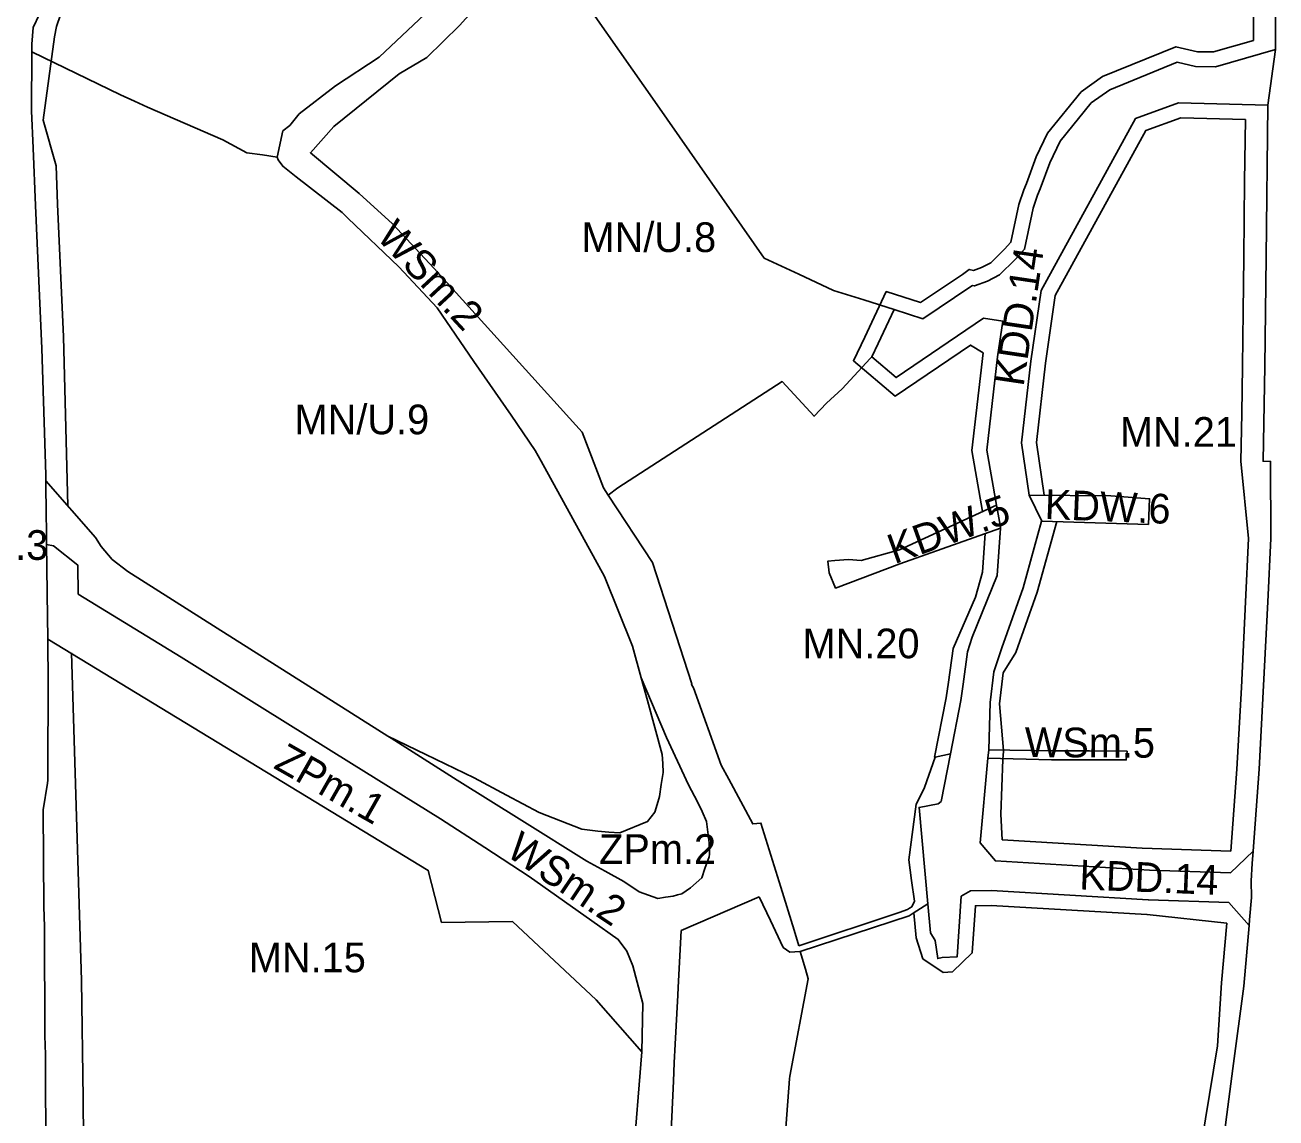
# Model space of a CAD drawing. Extents: x 7431080 to 7433370, y 5546450 to 5548428.
# Drawn here: x 7431653 to 7431989.9, y 5547216.3 to 5547510.7 of the extents above; entities that cross this region are included whole.
import ezdxf

# ---------------------------------------------------------------- set-up
doc = ezdxf.new("R2010")
doc.units = 0
for name, color, linetype in [('Linie Rozgraniczajace', 7, 'Continuous'), ('nieprzekraczalna linia zabudowy', 7, 'Continuous'), ('oznaczenia_przeznaczen', 7, 'Continuous')]:
    doc.layers.add(name, color=color, linetype=linetype)

msp = doc.modelspace()

# ---------------------------------------------------------------- linework, layer by layer
at = {"layer": 'Linie Rozgraniczajace'}
for p, q in [((7431911.15, 5547431.69), (7431916.34, 5547430.94)), ((7431658.88, 5547364.65), (7431658.97, 5547357.52)), ((7431829.74, 5547266.75), (7431850.69, 5547275.88)), ((7431850.69, 5547275.88), (7431853.77, 5547269.44)), ((7431829.74, 5547266.75), (7431828.91, 5547251.44))]:
    msp.add_line(p, q, dxfattribs=at)
for points in [[(7431654.75, 5547487.52), (7431654.85, 5547503.43), (7431654.86, 5547505.49), (7431655.24, 5547510.04), (7431661.99, 5547524.42), (7431663.48, 5547526.4), (7431672.06, 5547534.63), (7431672.08, 5547534.66), (7431672.12, 5547534.69), (7431679.18, 5547541.67), (7431679.27, 5547541.81), (7431679.43, 5547541.93), (7431683.86, 5547546.88), (7431683.88, 5547546.91), (7431684.29, 5547547.41), (7431690.25, 5547555.79), (7431706.15, 5547576.86), (7431734.93, 5547609.85), (7431751.33, 5547628.73)], [(7431989.92, 5547534.61), (7431989.83, 5547504.09), (7431987.71, 5547489.08), (7431987.25, 5547448.13), (7431986.91, 5547418.82), (7431986.45, 5547393.18), (7431988.46, 5547393.1), (7431988.49, 5547372.36), (7431987.7, 5547355.33), (7431985.39, 5547310.25), (7431983.79, 5547288.13), (7431983.55, 5547284.77), (7431983.22, 5547280.11), (7431983.37, 5547275.64), (7431982.82, 5547269.6), (7431982.69, 5547268.13)], [(7431722.46, 5547482.18), (7431724.32, 5547483.59), (7431726.87, 5547486.76), (7431736.59, 5547494.28), (7431748.4, 5547502), (7431779.07, 5547531.01)], [(7431810.1, 5547384.01), (7431808.82, 5547385.97), (7431803.09, 5547401.04), (7431763.17, 5547445.1), (7431751.95, 5547457.15), (7431743.02, 5547465.27), (7431729.86, 5547476.25), (7431736.2, 5547483.32), (7431753.76, 5547497.55), (7431761.26, 5547501.96), (7431770.04, 5547510.52), (7431781.06, 5547522.88), (7431786.34, 5547526.6), (7431796.46, 5547527.5), (7431809.81, 5547528.69)], [(7431852.09, 5547447.88), (7431823.24, 5547489.18), (7431796.46, 5547527.5)], [(7431989.83, 5547504.09), (7431973.64, 5547499.41), (7431968.27, 5547499.5), (7431963.3, 5547500.63), (7431945.13, 5547493.25), (7431940.18, 5547489.7), (7431931.83, 5547479.42), (7431929.03, 5547473.59), (7431926.42, 5547466.52)], [(7431654.85, 5547503.43), (7431678.73, 5547491.84), (7431682.47, 5547490.14), (7431685.99, 5547488.55), (7431696.13, 5547484.12), (7431706.28, 5547479.7), (7431712.79, 5547476.27), (7431716.95, 5547475.66), (7431720.95, 5547475.06)], [(7431657.53, 5547423.57), (7431655.86, 5547462.08), (7431655.17, 5547477.51), (7431654.75, 5547487.52)], [(7431987.71, 5547489.08), (7431963.67, 5547489.69), (7431952.08, 5547485.52), (7431926.64, 5547439.12)], [(7431739.95, 5547458.68), (7431738.42, 5547460.15), (7431726.08, 5547469.74), (7431722.43, 5547472.61), (7431721.17, 5547474.4), (7431720.95, 5547475.06), (7431722.46, 5547482.18)], [(7431926.42, 5547466.52), (7431925.72, 5547464.87), (7431924.54, 5547461.32), (7431922.23, 5547450.26), (7431919.69, 5547447.53), (7431915.47, 5547443.36), (7431912.21, 5547441.68), (7431908.72, 5547440.41), (7431908.18, 5547440.54), (7431907.75, 5547440.23), (7431894.85, 5547431.54), (7431887.09, 5547434.01), (7431882.76, 5547424.86), (7431881.05, 5547421.28), (7431887.61, 5547415.72), (7431911.15, 5547431.69)], [(7431792, 5547393.21), (7431790.45, 5547396.03), (7431783.97, 5547405.56), (7431773.85, 5547420.05), (7431764.05, 5547434.45), (7431753.65, 5547445.52), (7431739.95, 5547458.68)], [(7431852.09, 5547447.88), (7431861.44, 5547443.54), (7431870.78, 5547439.2), (7431878.94, 5547436.61), (7431887.09, 5547434.01)], [(7431926.64, 5547439.12), (7431923.87, 5547420.13), (7431921.36, 5547398.16), (7431923.46, 5547384.02), (7431926.84, 5547377.02)], [(7431916.34, 5547430.94), (7431914.94, 5547421.28), (7431912.07, 5547396.17), (7431914.68, 5547381.36), (7431915.72, 5547375.5)], [(7431658.73, 5547378.32), (7431658.61, 5547387.92), (7431658.59, 5547389.41), (7431658.58, 5547389.46), (7431658.58, 5547389.52), (7431657.53, 5547423.57)], [(7431881.05, 5547421.28), (7431880.66, 5547420.86), (7431873.05, 5547412.67), (7431868.84, 5547408.78)], [(7431868.84, 5547408.78), (7431865.51, 5547405.28), (7431856.93, 5547414.63), (7431812.71, 5547386.04), (7431810.1, 5547384.01)], [(7431816.62, 5547343.35), (7431809.1, 5547362.1), (7431792, 5547393.21)], [(7431823.41, 5547275.41), (7431818.42, 5547277.14), (7431814.31, 5547279.98), (7431809.3, 5547282.71), (7431804.29, 5547285.44), (7431786.85, 5547296.36), (7431769.41, 5547307.27), (7431751.61, 5547318.54), (7431750.72, 5547319.1), (7431733.81, 5547329.8), (7431704.74, 5547348.23), (7431680.68, 5547363.49), (7431676.51, 5547366.67), (7431673.51, 5547370.24), (7431672.04, 5547372.61), (7431658.61, 5547387.92)], [(7431842.55, 5547307.5), (7431840.48, 5547311.34), (7431833.02, 5547332.1), (7431832.55, 5547333.05), (7431832.58, 5547333.2), (7431821.99, 5547365.86), (7431810.1, 5547384.01)], [(7431926.8, 5547377.02), (7431926.84, 5547377.02), (7431955.55, 5547376.16), (7431955.86, 5547383.06), (7431945.43, 5547383.88), (7431923.46, 5547384.02)], [(7431915.69, 5547375.17), (7431888.6, 5547365.55), (7431871.3, 5547358.99), (7431869.61, 5547363.12), (7431869.24, 5547366.28), (7431871.15, 5547366.42), (7431874.76, 5547366.67), (7431878.19, 5547366.44), (7431888.55, 5547369.29), (7431914.68, 5547381.36)], [(7431658.88, 5547364.65), (7431658.81, 5547370.74), (7431658.8, 5547371.77), (7431658.77, 5547375.04), (7431658.73, 5547378.32)], [(7431926.8, 5547377.02), (7431921.8, 5547359.07), (7431916.11, 5547342.95), (7431913.9, 5547336.43), (7431912.93, 5547328.15), (7431912.55, 5547315.41), (7431912.35, 5547313.16), (7431910.27, 5547290.41)], [(7431915.72, 5547375.5), (7431915.69, 5547375.17), (7431914.86, 5547362.36), (7431908.07, 5547345.81), (7431906.88, 5547341.87), (7431905.67, 5547333.14), (7431905.03, 5547328.75), (7431902.24, 5547314.38), (7431899.74, 5547301.55)], [(7431667.36, 5547357.35), (7431667.23, 5547365.2), (7431660.65, 5547370.39), (7431658.81, 5547370.74)], [(7431658.97, 5547357.52), (7431659.12, 5547345.2), (7431761.61, 5547282.96), (7431765.2, 5547268.96), (7431784.34, 5547269.17), (7431806.85, 5547248.07), (7431819.14, 5547234.05), (7431816.7, 5547204.08)], [(7431819.14, 5547234.05), (7431819.41, 5547247.06), (7431816.67, 5547257.29), (7431815.11, 5547261.17), (7431812.76, 5547264.35), (7431805.63, 5547269.4), (7431788.81, 5547281.31), (7431776.88, 5547289.08), (7431764.95, 5547296.84), (7431740.92, 5547311.77), (7431716.88, 5547326.7), (7431695.09, 5547340.42), (7431667.36, 5547357.35)], [(7431658.49, 5547233.33), (7431658.4, 5547235.87), (7431658.38, 5547238.37), (7431658.23, 5547267.77), (7431658.09, 5547273.21), (7431657.89, 5547299.24), (7431659.11, 5547306.48), (7431659.17, 5547307.29), (7431659.2, 5547307.47), (7431659.23, 5547336.06), (7431659.22, 5547336.1), (7431659.23, 5547336.14), (7431659.15, 5547342.23), (7431659.12, 5547345.2)], [(7431816.62, 5547343.35), (7431818.95, 5547334.86), (7431820.63, 5547328.75), (7431824.65, 5547314.14), (7431824.75, 5547311.72), (7431824.84, 5547309.3), (7431824.36, 5547306.08), (7431823.88, 5547302.85), (7431823.28, 5547300.75), (7431822.67, 5547298.64), (7431821.69, 5547297.39), (7431820.7, 5547296.14), (7431813.2, 5547293.06), (7431810.25, 5547293.29), (7431807.29, 5547293.51), (7431805.12, 5547293.77), (7431802.95, 5547294.03), (7431797.22, 5547296.31), (7431791.49, 5547298.59), (7431782.73, 5547303.25), (7431773.97, 5547307.92), (7431760.95, 5547314.18), (7431750.72, 5547319.1)], [(7431834.1, 5547301.46), (7431831.73, 5547305.96), (7431828.78, 5547312.35), (7431825.82, 5547318.74), (7431818.95, 5547334.86)], [(7431949.87, 5547315.11), (7431949.59, 5547312.71), (7431929.5, 5547312.76), (7431912.35, 5547313.16)], [(7431949.87, 5547315.11), (7431939.71, 5547315.15), (7431929.55, 5547315.19), (7431912.55, 5547315.41)], [(7431902.24, 5547314.38), (7431898.1, 5547313.46), (7431895.29, 5547305.31), (7431893.79, 5547302.34)], [(7431856.57, 5547278.44), (7431851.21, 5547295.71), (7431849, 5547295.47), (7431842.55, 5547307.5)], [(7431893.79, 5547302.34), (7431893.03, 5547300.83), (7431891.03, 5547285.82)], [(7431899.74, 5547301.55), (7431898.97, 5547300.89), (7431893.79, 5547299.93), (7431896.18, 5547273.98), (7431896.9, 5547266.1), (7431898.14, 5547264.1), (7431898.81, 5547259.19), (7431900.04, 5547259.52), (7431904.05, 5547259.63), (7431905.13, 5547275.99), (7431907.64, 5547277.42), (7431913.31, 5547277.53)], [(7431833.77, 5547279.59), (7431835.29, 5547280.92), (7431836.13, 5547283.51), (7431837.23, 5547286.6), (7431837.35, 5547287.33), (7431837.25, 5547290.42), (7431836.59, 5547296.11), (7431835.34, 5547298.79), (7431834.1, 5547301.46)], [(7431910.27, 5547290.41), (7431914.35, 5547285.49), (7431955.89, 5547283.03), (7431977.67, 5547282.29), (7431983.79, 5547288.13)], [(7431861.38, 5547262.61), (7431888.46, 5547271.64), (7431890.67, 5547272.42), (7431891.25, 5547272.8), (7431891.82, 5547273.18), (7431892.53, 5547274.63), (7431891.78, 5547280.23), (7431891.03, 5547285.82)], [(7431823.41, 5547275.41), (7431825.47, 5547275.73), (7431827.53, 5547276.05), (7431828.7, 5547276.36), (7431829.87, 5547276.67), (7431832.25, 5547278.27)], [(7431832.25, 5547278.27), (7431833.77, 5547279.59)], [(7431861.38, 5547262.61), (7431860.14, 5547266.88), (7431856.57, 5547278.44)], [(7431913.31, 5547277.53), (7431955.47, 5547275.05), (7431955.55, 5547275.04), (7431977.18, 5547274.29), (7431982.69, 5547268.13)], [(7431853.77, 5547269.44), (7431857.23, 5547262.21), (7431858.11, 5547261.57), (7431858.98, 5547260.92), (7431860.36, 5547261), (7431861.81, 5547261.09), (7431891.1, 5547270.71), (7431892.2, 5547271.42), (7431896.18, 5547273.98)], [(7431982.69, 5547268.13), (7431981.23, 5547251.74), (7431978.31, 5547229.55), (7431974.71, 5547202.02), (7431970.19, 5547165.15), (7431968.19, 5547146.81), (7431967.04, 5547137.69), (7431965.97, 5547129.38), (7431958.32, 5547098.48), (7431950.67, 5547067.58), (7431946.36, 5547051.38), (7431942.22, 5547037.08), (7431940.3, 5547031.13), (7431931.28, 5547003.09), (7431929.38, 5546995.1), (7431925.81, 5546980.02), (7431923.56, 5546962.78), (7431922.79, 5546956.43), (7431922.55, 5546952.38), (7431922.4, 5546944.22), (7431924.59, 5546921)], [(7431861.81, 5547261.09), (7431863.2, 5547256.32), (7431863.94, 5547253.77)], [(7431828.91, 5547251.44), (7431828.8, 5547249.37), (7431828.08, 5547236.12), (7431827.86, 5547231.16), (7431827.63, 5547226.19)], [(7431863.94, 5547253.77), (7431859.01, 5547227.55)], [(7431658.63, 5547197.82), (7431658.6, 5547204.53), (7431658.49, 5547233.33)], [(7431859.01, 5547227.55), (7431858.87, 5547226.83), (7431854.38, 5547166.78), (7431852.22, 5547134.82)], [(7431807.96, 5546902.76), (7431808.69, 5546923.81), (7431809.32, 5546947.71), (7431811.09, 5546972.31), (7431812.99, 5547003.97), (7431813.23, 5547008.39), (7431815.18, 5547044.96), (7431818.54, 5547093.2), (7431821.95, 5547136.09), (7431824.4, 5547166.73), (7431825.46, 5547180), (7431826.45, 5547201.22), (7431827.63, 5547226.19)]]:
    msp.add_lwpolyline(points, dxfattribs=at)
at = {"layer": 'nieprzekraczalna linia zabudowy'}
for points in [[(7431806.44, 5547718.75), (7431805.15, 5547715.73), (7431796.7, 5547695.18), (7431787.22, 5547671.1), (7431780.71, 5547658.46), (7431773.52, 5547646.38), (7431768.89, 5547639.91), (7431764.71, 5547635.1), (7431739.04, 5547605.53), (7431721.59, 5547588.87), (7431699.41, 5547558.7), (7431690.62, 5547545.91), (7431687.1, 5547541.4), (7431683.8, 5547537.89), (7431672.34, 5547526.7), (7431666.86, 5547521.31), (7431664.37, 5547517.37), (7431662.55, 5547513.39), (7431661.48, 5547510.3), (7431660.93, 5547507.5), (7431657.89, 5547485.06)], [(7431983.84, 5547506.52), (7431983.92, 5547534.63), (7431984.29, 5547579.58)], [(7431911.03, 5547422.33), (7431907.63, 5547424.47), (7431887.34, 5547410.7), (7431876.11, 5547420.22), (7431879.15, 5547426.58), (7431884.97, 5547438.88), (7431894.22, 5547435.94), (7431905.46, 5547443.51), (7431907.33, 5547444.86), (7431908.48, 5547444.58), (7431910.6, 5547445.35), (7431913.09, 5547446.64), (7431916.82, 5547450.32), (7431918.54, 5547452.17), (7431920.67, 5547462.36), (7431921.97, 5547466.28), (7431922.7, 5547467.99), (7431925.34, 5547475.15), (7431928.43, 5547481.58), (7431937.41, 5547492.64), (7431943.18, 5547496.79), (7431962.96, 5547504.81), (7431968.75, 5547503.49), (7431973.11, 5547503.42), (7431983.84, 5547506.52)], [(7431657.89, 5547485.06), (7431661.39, 5547472.78), (7431661.8, 5547462.44)], [(7431981.67, 5547485.23), (7431964.32, 5547485.67), (7431954.86, 5547482.27), (7431930.49, 5547437.83), (7431927.84, 5547419.61), (7431925.39, 5547398.23), (7431927.51, 5547384)], [(7431977.79, 5547288.13), (7431978.59, 5547299.19), (7431979.39, 5547310.25), (7431980.59, 5547332.23), (7431981.7, 5547355.33), (7431982.49, 5547372.36), (7431980.45, 5547393.18), (7431980.68, 5547406), (7431980.91, 5547418.82), (7431981.08, 5547433.48), (7431981.25, 5547448.13), (7431981.48, 5547468.61), (7431981.67, 5547485.23)], [(7431661.8, 5547462.44), (7431663.42, 5547426.71), (7431664.57, 5547381.12)], [(7431910.92, 5547379.63), (7431908.03, 5547396.05), (7431911.03, 5547422.33)], [(7431930.92, 5547376.9), (7431925.62, 5547357.87), (7431919.89, 5547341.64), (7431916.43, 5547336.14), (7431915.46, 5547327.86), (7431916.55, 5547315.25), (7431916.53, 5547315.03), (7431916.33, 5547312.8), (7431915.79, 5547298.11), (7431916.21, 5547291.16)], [(7431897.98, 5547313.43), (7431901.09, 5547329.42), (7431901.71, 5547333.7), (7431902.96, 5547342.73), (7431909.02, 5547356.58), (7431910.91, 5547363.27), (7431911.59, 5547373.71)], [(7431665.52, 5547341.53), (7431668.21, 5547253.27), (7431668.7, 5547221.52), (7431668.87, 5547199.43)], [(7431916.21, 5547291.16), (7431953.88, 5547288.93), (7431977.79, 5547288.12)], [(7431894.78, 5547259.1), (7431893, 5547264.8), (7431892.39, 5547271.54)], [(7431976.69, 5547268.76), (7431955.23, 5547271.05), (7431955.1, 5547271.06), (7431913.23, 5547273.53), (7431908.97, 5547273.45), (7431908.13, 5547260.72), (7431902.8, 5547255.59)], [(7431930.13, 5546857.16), (7431928.18, 5546875.52), (7431925.16, 5546882.4), (7431919.72, 5546910.16), (7431918.61, 5546921.06), (7431916.4, 5546944.52), (7431916.55, 5546952.98), (7431916.8, 5546957.24), (7431918.92, 5546968.75), (7431919.87, 5546981.19), (7431923.49, 5546996.47), (7431925.42, 5547004.61), (7431934.49, 5547032.8), (7431936.39, 5547038.7), (7431940.51, 5547052.9), (7431944.8, 5547069.02), (7431960.03, 5547130.57), (7431961.07, 5547138.64), (7431962.22, 5547147.72), (7431964.22, 5547166.06), (7431968.74, 5547202.97), (7431974.16, 5547235.72), (7431975.25, 5547252.63), (7431976.69, 5547268.76)], [(7431902.8, 5547255.59), (7431900.29, 5547255.45), (7431894.78, 5547259.1)]]:
    msp.add_lwpolyline(points, dxfattribs=at)

# ---------------------------------------------------------------- texts
at = {"layer": 'oznaczenia_przeznaczen'}
for s, rotation, p in [('WSm.2', 312.8961, (7431747.37, 5547453.45)), ('KDD.14', 81.5764, (7431921.92, 5547413.09)), ('KDW.5', 19.7723, (7431887.14, 5547365.39)), ('KDW.6', 357.7267, (7431927.53, 5547377.63)), ('WSm.5', 359.7103, (7431922.25, 5547313.48)), ('ZPm.1', 330.3938, (7431719.65, 5547310.65)), ('ZPm.1', 330.3938, (7431719.65, 5547310.65)), ('ZPm.1', 330.3938, (7431719.65, 5547310.65)), ('WSm.2', 326.0658, (7431782.19, 5547287.18)), ('WSm.2', 326.0658, (7431782.19, 5547287.18)), ('KDD.14', 357.6816, (7431936.85, 5547277.86))]:
    msp.add_text(s, height=8, rotation=rotation, dxfattribs=at).set_placement(p)
for s, p in [('MN/U.8', (7431802.9, 5547449.52)), ('MN/U.9', (7431725.61, 5547400.43)), ('MN.21', (7431947.9, 5547397.06)), ('ZPb.3', (7431630.73, 5547366.6)), ('ZPb.3', (7431630.73, 5547366.6)), ('MN.20', (7431862.42, 5547340.09)), ('ZPm.2', (7431807.62, 5547284.7)), ('MN.15', (7431713.3, 5547255.51))]:
    msp.add_text(s, height=8, dxfattribs=at).set_placement(p)

doc.saveas('drawing.dxf')
